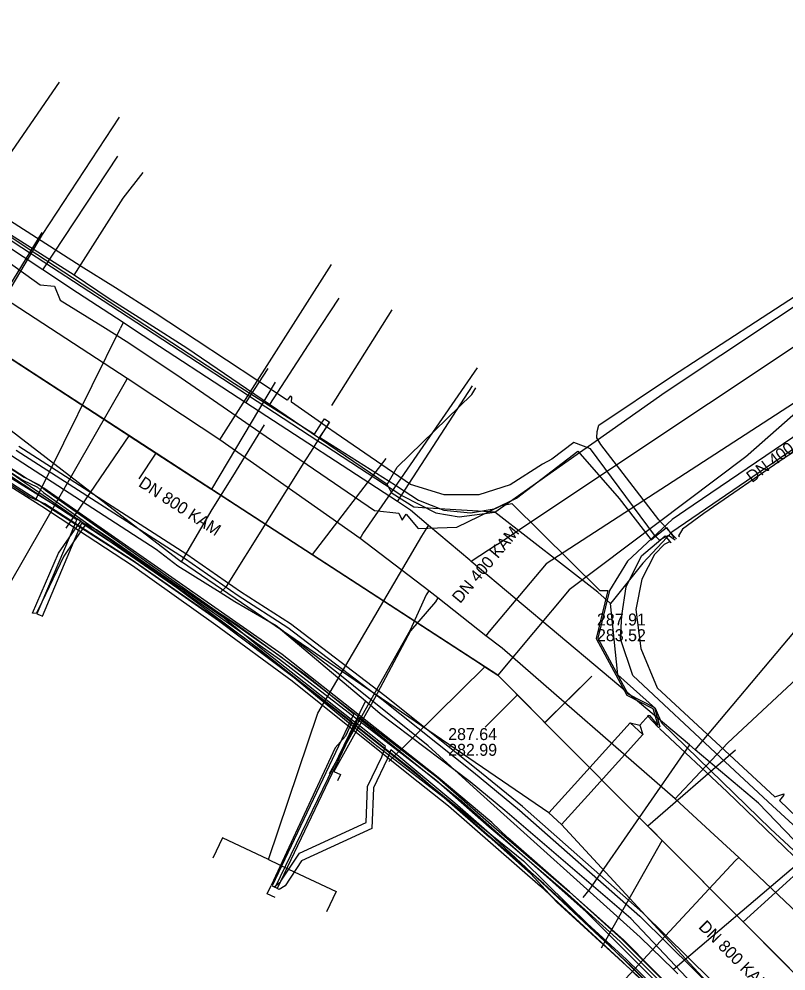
# Model space of a CAD drawing. Extents: x -600309 to -598967, y -1161267 to -1160292.
# Drawn here: x -599995.5 to -599944.1, y -1160430.9 to -1160367.2 of the extents above; entities that cross this region are included whole.
import ezdxf

# ---------------------------------------------------------------- set-up
doc = ezdxf.new("R2010")
doc.units = 0
for name, color, linetype in [('Vrstva 1', 7, 'Continuous'), ('Vrstva 12', 7, 'Continuous'), ('Vrstva 13', 7, 'Continuous'), ('Vrstva 16', 7, 'Continuous'), ('Vrstva 42', 7, 'Continuous'), ('Vrstva 44', 7, 'Continuous'), ('Vrstva 54', 7, 'Continuous'), ('Vrstva 55', 7, 'Continuous'), ('Vrstva 58', 7, 'Continuous'), ('Vrstva 9', 7, 'Continuous')]:
    doc.layers.add(name, color=color, linetype=linetype)

msp = doc.modelspace()

# ---------------------------------------------------------------- linework, layer by layer
at = {"layer": 'Vrstva 1'}
for p, q in [((-599987.41, -1160397.98), (-599986.289, -1160396.256)), ((-599957.13, -1160411.18), (-599960.263, -1160414.296)), ((-599964.26, -1160414.59), (-599962.102, -1160412.446))]:
    msp.add_line(p, q, dxfattribs=at)
for points in [[(-599960.264, -1160414.296), (-599962.102, -1160412.446), (-599963.42, -1160411.12), (-599980.529, -1160400), (-599986.289, -1160396.256), (-599998.233, -1160388.493), (-600002.3, -1160385.85), (-600006.056, -1160383.17), (-600017.139, -1160375.261), (-600022.533, -1160371.412), (-600032.76, -1160364.114), (-600036.59, -1160361.38), (-600042, -1160357.52)], [(-599987.41, -1160397.98), (-599986.29, -1160396.26)], [(-599957.13, -1160411.18), (-599960.26, -1160414.3)], [(-599964.26, -1160414.59), (-599962.102, -1160412.446)], [(-599857.52, -1160559.89), (-599866.111, -1160548.18), (-599871.76, -1160540.48), (-599878.734, -1160527.773), (-599886.327, -1160513.932), (-599890.764, -1160505.846), (-599893.889, -1160500), (-599898.969, -1160490.471), (-599901.936, -1160484.905), (-599902.158, -1160484.489), (-599906.15, -1160477), (-599907.435, -1160475.222), (-599915.237, -1160464.873), (-599922.471, -1160455.22), (-599931.32, -1160443.41), (-599941.55, -1160433.12), (-599946.993, -1160427.644), (-599952.415, -1160422.19), (-599953.381, -1160421.219)]]:
    msp.add_lwpolyline(points, dxfattribs=at)
at = {"layer": 'Vrstva 12'}
for points in [[(-600023.28, -1160363.85), (-599995.26, -1160382.49), (-599989.32, -1160386.36)], [(-599963.61, -1160400.2), (-599952.22, -1160392.16), (-599941.05, -1160384.74), (-599935.56, -1160381.31), (-599924.59, -1160374.96)], [(-599991.77, -1160384.34), (-600002.25, -1160377.7)], [(-599991.77, -1160384.34), (-599988.48, -1160379.19), (-599987.16, -1160377.46)], [(-599973.19, -1160414.27), (-599980.44, -1160408.6), (-599983.72, -1160406.31), (-599987.95, -1160403.37), (-599993.73, -1160399.64), (-599994.74, -1160399.21), (-599997.36, -1160397.53), (-600000.73, -1160395.37), (-600004.83, -1160392.84), (-600017.04, -1160384.87), (-600019.55, -1160383.22), (-600019.64, -1160383.16)], [(-599978.7, -1160393), (-599984.23, -1160389.23), (-599986.75, -1160387.62), (-599989.42, -1160385.91), (-599991.77, -1160384.34)], [(-599974.06, -1160385.87), (-599975.81, -1160388.55)], [(-599989.32, -1160386.36), (-599975.46, -1160395.42)], [(-599975.81, -1160388.55), (-599978.7, -1160393)], [(-599970.82, -1160398.36), (-599970.16, -1160397.2), (-599965.16, -1160392.32), (-599964.88, -1160391.89)], [(-599981.99, -1160405.59), (-599984.83, -1160403.82), (-599986.28, -1160402.71), (-599996.74, -1160395.94), (-599999.28, -1160394.3), (-600000.59, -1160393.46), (-600001.197, -1160393.068)], [(-599970.82, -1160398.36), (-599978.7, -1160393)], [(-599975.46, -1160395.42), (-599974.71, -1160394.23)], [(-599942.26, -1160395.06), (-599951.77, -1160401.55), (-599953.71, -1160403.62), (-599955.67, -1160406.08), (-599955.87, -1160406.32)], [(-599975.89, -1160396.11), (-599975.46, -1160395.42)], [(-599975.46, -1160395.42), (-599975, -1160395.71)], [(-599975, -1160395.71), (-599969.83, -1160399.09), (-599967.56, -1160400.24), (-599966, -1160400.51), (-599963.61, -1160400.2)], [(-599981.99, -1160405.59), (-599981.58, -1160405.18), (-599976.27, -1160396.71), (-599975.89, -1160396.11)], [(-599968.46, -1160399.91), (-599969.03, -1160399.88), (-599970.49, -1160398.95), (-599970.82, -1160398.36)], [(-599963.61, -1160400.2), (-599968.46, -1160399.91)], [(-599955.87, -1160406.32), (-599956.73, -1160405.55), (-599963.61, -1160400.2)], [(-599978.26, -1160407.82), (-599981.01, -1160406.2), (-599981.99, -1160405.59)], [(-599939.98, -1160426.23), (-599945.17, -1160421.41), (-599952.43, -1160414.33), (-599952.87, -1160413.35), (-599955.39, -1160411.09), (-599955.87, -1160406.32)], [(-599977.97, -1160408.04), (-599978.26, -1160407.82)], [(-599972.28, -1160412.85), (-599978.26, -1160407.82)], [(-599964.8, -1160418.85), (-599968.07, -1160415.86), (-599974.32, -1160410.82), (-599977.97, -1160408.04)], [(-599978.32, -1160425.33), (-599972.28, -1160412.85)], [(-599971.28, -1160413.7), (-599972.28, -1160412.85)], [(-599944.48, -1160438.01), (-599950.78, -1160431.36), (-599954.51, -1160427.4), (-599962.95, -1160420.18), (-599965.27, -1160418.25), (-599971.28, -1160413.7)], [(-599973.19, -1160414.27), (-599968.97, -1160417.58), (-599967.01, -1160419.31), (-599964, -1160421.95), (-599961.23, -1160424.4), (-599959.47, -1160426.32), (-599952.75, -1160432.45), (-599949.48, -1160435.72)], [(-599951.66, -1160430.83), (-599953.9, -1160428.65), (-599964.8, -1160418.85)], [(-599978.31, -1160426.01), (-599978.85, -1160425.76), (-599978.59, -1160425.2)], [(-599951.37, -1160431.11), (-599951.66, -1160430.83)]]:
    msp.add_lwpolyline(points, dxfattribs=at)
at = {"layer": 'Vrstva 13'}
for p, q in [((-599960.18, -1160403.66), (-599963.99, -1160408.2)), ((-599963.99, -1160408.2), (-599964.22, -1160408.49))]:
    msp.add_line(p, q, dxfattribs=at)
for points in [[(-599964.22, -1160408.49), (-599967.42, -1160405.94), (-599968.03, -1160405.48), (-599972.62, -1160401.96), (-599982.02, -1160395.37), (-599984.52, -1160393.71), (-599988.214, -1160391.255), (-599996.42, -1160385.9), (-600005.77, -1160380.17), (-600008.31, -1160378.57), (-600012.56, -1160375.88), (-600019.267, -1160371.34), (-600024.36, -1160367.73), (-600031.52, -1160362.48), (-600033.31, -1160361.09), (-600035.67, -1160359.28), (-600040.26, -1160355.47), (-600042.33, -1160353.69)], [(-599894.43, -1160365.84), (-599902.54, -1160369.63), (-599909.986, -1160373.19), (-599920.605, -1160378.688), (-599921.207, -1160379.075), (-599936.343, -1160388.199), (-599960.18, -1160403.66)], [(-599996.42, -1160385.9), (-599996.283, -1160385.655), (-599993.88, -1160381.62), (-599988.727, -1160373.768)], [(-599982.02, -1160395.37), (-599981.9, -1160395.19), (-599974.542, -1160383.628)], [(-599972.62, -1160401.96), (-599972.44, -1160401.66), (-599964.787, -1160390.548)], [(-599988.214, -1160391.255), (-599988.36, -1160391.51), (-599997.209, -1160406.931)], [(-599968.03, -1160405.48), (-599968.21, -1160405.73), (-599969.29, -1160408.11), (-599971.82, -1160412.61), (-599974.701, -1160417.734)], [(-599967.42, -1160405.94), (-599967.59, -1160406.2), (-599969.26, -1160408.15), (-599971.68, -1160412.67), (-599974.39, -1160417.57), (-599973.94, -1160417.78), (-599974.142, -1160418.185)], [(-599902.667, -1160478.427), (-599912.9, -1160463.23), (-599924.79, -1160447.56), (-599925.44, -1160446.75), (-599932.72, -1160438.46), (-599934.77, -1160436.27), (-599943.79, -1160426.66), (-599947.29, -1160423.32), (-599949.5, -1160421.29), (-599951.54, -1160419.4), (-599963.13, -1160409.31), (-599964.22, -1160408.49)], [(-599951.54, -1160419.4), (-599951.31, -1160419.14), (-599948.03, -1160415.65), (-599940.131, -1160408.289)], [(-599973.19, -1160414.27), (-599973.62, -1160415.21), (-599974.31, -1160415.98), (-599978.59, -1160425.2)], [(-599947.29, -1160423.32), (-599947.51, -1160423.53), (-599961.629, -1160438.72), (-599962.193, -1160440.043)], [(-599942.88, -1160423.87), (-599943.15, -1160423.61), (-599943.78, -1160424.14), (-599951.4, -1160430.61), (-599951.66, -1160430.83)]]:
    msp.add_lwpolyline(points, dxfattribs=at)
at = {"layer": 'Vrstva 16'}
for points in [[(-599963.47, -1160402.36), (-599961.01, -1160400.72), (-599937.64, -1160385.15), (-599923.8, -1160377.08), (-599919.49, -1160374.56), (-599912.45, -1160370.78), (-599905.14, -1160366.86), (-599900.61, -1160364.43), (-599893.63, -1160361.35), (-599891.35, -1160360.35), (-599884.67, -1160357.41), (-599873.32, -1160353), (-599871.361, -1160352.261), (-599865.52, -1160350.14), (-599865.3, -1160350.05), (-599864.88, -1160349.89), (-599860.27, -1160348.08), (-599856.17, -1160346.52), (-599819.83, -1160335.69), (-599819.46, -1160335.48), (-599819.06, -1160335.44)], [(-599965.28, -1160403.42), (-599968.05, -1160401.09), (-599969.25, -1160400.08), (-599970.14, -1160399.5), (-599980.29, -1160392.89), (-599987.66, -1160388.06), (-599988.499, -1160387.509), (-599991.54, -1160385.51), (-599993.86, -1160383.97), (-600004.55, -1160376.92), (-600004.622, -1160376.872), (-600013.7, -1160370.88), (-600015.76, -1160369.53), (-600021.6, -1160365.66), (-600038.95, -1160354.2)], [(-599993.86, -1160383.97), (-599988.84, -1160376.36)], [(-599988.499, -1160387.509), (-599988.671, -1160387.887)], [(-599994.354, -1160399.412), (-599988.671, -1160387.887)], [(-599980.29, -1160392.89), (-599978.79, -1160390.59)], [(-599970.14, -1160399.5), (-599965.11, -1160391.74)], [(-599978.76, -1160423.46), (-599975.46, -1160413.662), (-599968.5, -1160401.82), (-599968.05, -1160401.09)], [(-599963.47, -1160402.36), (-599965.19, -1160403.5)], [(-599965.19, -1160403.5), (-599965.28, -1160403.42)], [(-599902.03, -1160473.66), (-599906.22, -1160466.83), (-599917.21, -1160451.71), (-599919.38, -1160448.9), (-599921.83, -1160445.73), (-599925.66, -1160440.77), (-599928.37, -1160437.95), (-599940.64, -1160425.22), (-599945.97, -1160419.69), (-599950.21, -1160416.11), (-599950.59, -1160415.79), (-599965.19, -1160403.5)], [(-599950.21, -1160416.11), (-599943.49, -1160408.12)], [(-599950.59, -1160415.79), (-599957.33, -1160425.52)], [(-599978.76, -1160423.46), (-599981.83, -1160422), (-599982.48, -1160423.36)], [(-599978.76, -1160423.46), (-599977.42, -1160424.1), (-599974.24, -1160425.61), (-599974.89, -1160426.97)], [(-599957.33, -1160425.52), (-599957.73, -1160426)]]:
    msp.add_lwpolyline(points, dxfattribs=at)
at = {"layer": 'Vrstva 42'}
for points in [[(-599951.47, -1160402), (-599951.968, -1160401.459), (-599952.156, -1160401.256), (-599952.65, -1160400.72), (-599956.53, -1160395.68), (-599956.78, -1160395.23), (-599956.77, -1160394.8), (-599956.65, -1160394.38), (-599951.72, -1160391.08), (-599946.17, -1160387.45), (-599940.44, -1160383.74), (-599936.705, -1160381.356), (-599936.21, -1160381.04), (-599934.41, -1160379.87), (-599934.37, -1160379.3), (-599933.9, -1160379.61), (-599928.97, -1160376.92), (-599921.24, -1160372.43), (-599915.61, -1160369.42), (-599907.76, -1160365.37), (-599902.03, -1160362.65), (-599901.43, -1160361.97), (-599899.98, -1160359.11), (-599899.98, -1160359.02)], [(-599997.635, -1160379.114), (-599997.91, -1160379.524), (-599997.995, -1160379.651), (-599997.381, -1160380.028), (-599997.304, -1160379.91), (-599996.512, -1160378.696), (-599996.13, -1160376.351), (-599992.76, -1160371.421)], [(-599951.549, -1160402.07), (-599952.006, -1160401.772), (-599952.163, -1160401.857), (-599952.508, -1160402.043), (-599952.588, -1160402.086), (-599952.861, -1160401.813), (-599952.934, -1160401.741), (-599957.204, -1160395.967), (-599958.338, -1160395.539), (-599959.808, -1160396.653), (-599960.419, -1160396.989), (-599962.599, -1160398.374), (-599964.694, -1160399.048), (-599967.016, -1160399.054), (-599969.258, -1160398.361), (-599974.232, -1160394.938), (-599974.878, -1160394.485), (-599975.206, -1160394.256), (-599977.22, -1160392.844), (-599977.204, -1160392.513), (-599977.321, -1160392.439), (-599977.514, -1160392.703), (-599983.612, -1160388.696), (-599986.342, -1160386.873), (-599989.004, -1160385.192), (-599991.29, -1160383.748), (-599997.304, -1160379.91)], [(-599998.675, -1160380.016), (-599994.262, -1160382.926), (-599981.035, -1160391.583), (-599975.686, -1160394.973), (-599975.206, -1160394.256), (-599975.007, -1160393.959), (-599974.841, -1160394.07), (-599974.675, -1160394.182), (-599974.878, -1160394.485), (-599975.348, -1160395.187), (-599970.272, -1160398.403), (-599968.724, -1160399.394), (-599967.024, -1160400.077), (-599965.244, -1160400.254), (-599963.652, -1160399.976), (-599962.168, -1160399.267), (-599958.068, -1160396.13), (-599955.288, -1160399.284), (-599953.16, -1160402.049), (-599952.861, -1160401.813), (-599952.156, -1160401.256), (-599952.134, -1160401.239), (-599951.968, -1160401.459), (-599951.626, -1160401.915)], [(-599974.531, -1160393.052), (-599970.483, -1160386.651)], [(-599938.19, -1160392.68), (-599944.25, -1160396.58), (-599949.63, -1160400.29), (-599951.06, -1160401.35), (-599951.333, -1160401.782), (-599951.257, -1160401.866)], [(-599889.647, -1160517.995), (-599897.979, -1160502.841), (-599899.24, -1160500.71), (-599900.77, -1160497.971), (-599903.241, -1160493.768), (-599915.215, -1160473.333), (-599916.653, -1160471.11), (-599922.846, -1160462.646), (-599925.156, -1160459.335), (-599929.695, -1160453.144), (-599937.912, -1160443.505), (-599940.759, -1160440.186), (-599941.982, -1160438.954), (-599944.593, -1160436.033), (-599953.705, -1160427.041), (-599961.766, -1160419.921), (-599964.861, -1160417.387), (-599970.985, -1160412.494), (-599977.288, -1160407.684), (-599980.633, -1160405.531), (-599984.223, -1160403.04), (-599995.48, -1160395.806)], [(-599889.647, -1160517.995), (-599897.979, -1160502.841), (-599899.24, -1160500.71), (-599900.77, -1160497.971), (-599903.241, -1160493.768), (-599915.215, -1160473.333), (-599916.653, -1160471.11), (-599922.846, -1160462.646), (-599925.156, -1160459.335), (-599929.695, -1160453.144), (-599937.912, -1160443.505), (-599940.759, -1160440.186), (-599941.982, -1160438.954), (-599944.593, -1160436.033), (-599953.705, -1160427.041), (-599961.766, -1160419.921), (-599964.861, -1160417.387), (-599970.985, -1160412.494), (-599977.288, -1160407.684), (-599980.633, -1160405.531), (-599984.223, -1160403.04), (-599995.48, -1160395.806)], [(-599995.64, -1160396.06), (-599984.39, -1160403.29), (-599980.8, -1160405.78)], [(-599995.64, -1160396.06), (-599984.39, -1160403.29), (-599980.8, -1160405.78)], [(-599997.579, -1160396.764), (-599992.755, -1160399.93), (-599991.585, -1160400.698), (-599992.11, -1160401.934), (-599993.933, -1160406.226), (-599994.263, -1160407.003), (-599994.079, -1160407.081), (-599993.895, -1160407.159), (-599991.76, -1160402.132), (-599991.246, -1160400.921), (-599991.025, -1160401.066), (-599985.457, -1160404.72), (-599980.957, -1160407.673), (-599976.218, -1160411.144), (-599973.05, -1160413.713), (-599973.228, -1160414.087), (-599978.517, -1160425.218), (-599978.376, -1160425.285), (-599978.336, -1160425.304), (-599978.156, -1160425.39), (-599977.927, -1160424.908), (-599972.906, -1160414.342), (-599972.73, -1160413.972), (-599965.836, -1160419.563), (-599957.506, -1160426.969), (-599951.783, -1160432.676)], [(-599946.608, -1160438.419), (-599954.486, -1160430.597), (-599963.982, -1160421.725), (-599966.294, -1160419.68), (-599970.584, -1160416.109), (-599970.82, -1160416.739), (-599971.74, -1160418.672), (-599971.848, -1160421.385), (-599976.544, -1160423.541), (-599977.654, -1160425.22), (-599978.055, -1160425.458), (-599978.392, -1160425.298), (-599978.376, -1160425.285), (-599977.952, -1160424.946), (-599977.927, -1160424.908), (-599976.688, -1160423.034), (-599972.232, -1160420.988), (-599972.136, -1160418.573), (-599971.188, -1160416.581), (-599970.934, -1160415.903), (-599972.906, -1160414.342), (-599973.228, -1160414.087), (-599979.249, -1160409.322), (-599981.737, -1160407.312), (-599985.457, -1160404.72), (-599989.263, -1160402.068), (-599990.272, -1160401.389), (-599990.979, -1160401), (-599991.025, -1160401.066), (-599991.76, -1160402.132), (-599992.456, -1160403.14), (-599993.933, -1160406.226), (-599994.301, -1160406.995), (-599994.555, -1160406.958), (-599992.805, -1160402.941), (-599992.11, -1160401.934), (-599991.332, -1160400.807), (-599992.755, -1160399.93), (-599996.781, -1160397.449)], [(-599943.124, -1160421.628), (-599945.025, -1160419.86), (-599948.506, -1160416.624), (-599954.381, -1160411.147), (-599955.218, -1160408.693), (-599955.125, -1160407.122), (-599954.832, -1160405.211), (-599953.807, -1160403.137), (-599952.508, -1160402.043), (-599952.215, -1160401.796), (-599952.163, -1160401.857), (-599951.898, -1160402.167)], [(-599951.822, -1160402.269), (-599951.933, -1160402.196), (-599952.284, -1160402.372), (-599952.925, -1160403.037), (-599953.789, -1160404.7), (-599954.18, -1160406.719), (-599953.855, -1160409.324), (-599952.759, -1160411.967), (-599944.875, -1160419.258), (-599944.282, -1160419.062), (-599944.289, -1160419.186), (-599944.576, -1160419.52), (-599938.102, -1160425.728)], [(-599980.8, -1160405.78), (-599977.46, -1160407.93), (-599971.17, -1160412.73), (-599965.05, -1160417.62), (-599961.96, -1160420.15), (-599953.91, -1160427.26), (-599944.81, -1160436.24), (-599942.2, -1160439.16), (-599940.98, -1160440.39), (-599938.14, -1160443.7), (-599929.93, -1160453.33), (-599925.4, -1160459.51), (-599923.09, -1160462.82), (-599916.9, -1160471.28), (-599915.47, -1160473.49), (-599903.5, -1160493.92), (-599901.03, -1160498.12), (-599899.5, -1160500.86), (-599898.24, -1160502.99), (-599889.91, -1160518.14)], [(-599980.8, -1160405.78), (-599977.46, -1160407.93), (-599971.17, -1160412.73), (-599965.05, -1160417.62), (-599961.96, -1160420.15), (-599953.91, -1160427.26), (-599944.81, -1160436.24), (-599942.2, -1160439.16), (-599940.98, -1160440.39), (-599938.14, -1160443.7), (-599929.93, -1160453.33), (-599925.4, -1160459.51), (-599923.09, -1160462.82), (-599916.9, -1160471.28), (-599915.47, -1160473.49), (-599903.5, -1160493.92), (-599901.03, -1160498.12), (-599899.5, -1160500.86), (-599898.24, -1160502.99), (-599889.91, -1160518.14)]]:
    msp.add_lwpolyline(points, dxfattribs=at)
at = {"layer": 'Vrstva 44'}
for points in [[(-599905.38, -1160492.26), (-599906.11, -1160491.22), (-599907.117, -1160489.849), (-599907.718, -1160488.816), (-599912.251, -1160481.028), (-599913.037, -1160479.679), (-599914.197, -1160477.659), (-599918.207, -1160471.709), (-599928.467, -1160457.569), (-599929.807, -1160456.049), (-599934.317, -1160450.489), (-599945.727, -1160438.069), (-599951.097, -1160432.799), (-599954.977, -1160428.869), (-599958.627, -1160425.619), (-599962.747, -1160422.009), (-599963.807, -1160420.979), (-599967.407, -1160417.979), (-599977.847, -1160409.739), (-599993.787, -1160398.599), (-599995.027, -1160397.899), (-600016.677, -1160383.869)], [(-600001.81, -1160394.84), (-599993.94, -1160399.81), (-599987.86, -1160403.78), (-599982.28, -1160407.74), (-599977.18, -1160411.5), (-599969.28, -1160417.828), (-599966.72, -1160419.87), (-599960.55, -1160425.25), (-599955.02, -1160430.36), (-599948.81, -1160436.36), (-599943.48, -1160441.87), (-599937.91, -1160448.11), (-599932.55, -1160454.38), (-599927.36, -1160460.79), (-599922.23, -1160467.99), (-599917.44, -1160474.08), (-599913.386, -1160480.552), (-599912.49, -1160482), (-599908.85, -1160487.86), (-599907.3, -1160490.94)], [(-599917.3, -1160473.94), (-599922.07, -1160467.76), (-599927.18, -1160460.63), (-599932.29, -1160454.19), (-599937.65, -1160447.89), (-599943.36, -1160441.63), (-599948.66, -1160436.15), (-599954.81, -1160430.15), (-599960.34, -1160425.09), (-599966.51, -1160419.7), (-599971.73, -1160415.69), (-599977.04, -1160411.3), (-599982.1, -1160407.49), (-599987.69, -1160403.58), (-599993.78, -1160399.7), (-600001.64, -1160394.65)]]:
    msp.add_lwpolyline(points, dxfattribs=at)
at = {"layer": 'Vrstva 54'}
for points in [[(-600001.65, -1160390.39), (-599984.58, -1160403.54)], [(-599981.16, -1160397.82), (-599979.02, -1160394.36)], [(-599982.53, -1160400.02), (-599981.16, -1160397.82)], [(-599984.58, -1160403.54), (-599982.53, -1160400.02)], [(-599960.008, -1160420.332), (-599984.58, -1160403.54)], [(-599956.22, -1160416.15), (-599954.567, -1160414.319)], [(-599953.707, -1160415.092), (-599954.567, -1160414.319), (-599953.915, -1160414.459), (-599953.707, -1160415.092)], [(-599953.915, -1160414.459), (-599953.31, -1160413.79)], [(-599955.34, -1160416.9), (-599953.707, -1160415.092)], [(-599958.29, -1160418.43), (-599956.22, -1160416.15)], [(-599957.4, -1160419.18), (-599955.34, -1160416.9)], [(-599960.008, -1160420.332), (-599958.29, -1160418.43)], [(-599959.15, -1160421.108), (-599957.4, -1160419.18)], [(-599960.008, -1160420.332), (-599959.15, -1160421.108)], [(-599959.15, -1160421.108), (-599941.7, -1160440.04)]]:
    msp.add_lwpolyline(points, dxfattribs=at)
at = {"layer": 'Vrstva 55'}
for points in [[(-599997.25, -1160382.69), (-599994.04, -1160384.98), (-599993.09, -1160385.07), (-599992.7, -1160386), (-599989.85, -1160387.77), (-599988.1, -1160388.87), (-599984.609, -1160391.2), (-599979.35, -1160394.84), (-599971.66, -1160400.09), (-599970.045, -1160400.281), (-599969.81, -1160400.75), (-599969.55, -1160400.34), (-599968.739, -1160401.29), (-599966.159, -1160401.2), (-599963.179, -1160399.75), (-599962.479, -1160399.63), (-599956.58, -1160405.45), (-599956.052, -1160405.441), (-599956.844, -1160408.658), (-599954.794, -1160412.455), (-599953.04, -1160413.361), (-599952.707, -1160414.466), (-599953.231, -1160413.842), (-599953.41, -1160413.84), (-599952.683, -1160414.597), (-599952.59, -1160414.607)], [(-599937.803, -1160391.368), (-599937.909, -1160391.34), (-599938.649, -1160391.55), (-599938.929, -1160392.01), (-599941.87, -1160393.97), (-599950.337, -1160399.737), (-599951.75, -1160400.7), (-599954.74, -1160403.49), (-599955.932, -1160405.454), (-599956.716, -1160408.642), (-599954.706, -1160412.365), (-599952.94, -1160413.279), (-599952.575, -1160414.575)], [(-599952.589, -1160414.7), (-599948.07, -1160418.93), (-599939.74, -1160426.96)]]:
    msp.add_lwpolyline(points, dxfattribs=at)
at = {"layer": 'Vrstva 58'}
for points in [[(-600016.863, -1160384.098), (-599995.207, -1160398.053), (-599994.216, -1160398.54), (-599993.822, -1160398.879), (-599978.036, -1160410.049), (-599967.57, -1160418.126), (-599963.992, -1160421.264), (-599962.912, -1160422.195), (-599958.763, -1160425.764), (-599955.236, -1160428.951), (-599945.799, -1160438.408), (-599934.492, -1160450.715), (-599930.063, -1160456.185), (-599929.433, -1160456.793), (-599928.64, -1160457.944), (-599917.061, -1160474.028), (-599914.371, -1160477.772), (-599913.244, -1160479.838), (-599907.283, -1160489.98), (-599905.165, -1160493.525), (-599904.324, -1160495.376), (-599900.444, -1160501.778), (-599895.47, -1160511.178), (-599888.574, -1160523.607)], [(-600016.752, -1160383.932), (-599995.108, -1160397.869), (-599994.106, -1160398.371), (-599993.683, -1160398.732), (-599977.917, -1160409.889), (-599967.443, -1160417.972), (-599963.861, -1160421.113), (-599962.781, -1160422.043), (-599958.63, -1160425.614), (-599955.098, -1160428.806), (-599945.654, -1160438.27), (-599934.341, -1160450.583), (-599929.932, -1160456.041), (-599929.28, -1160456.665), (-599928.473, -1160457.834), (-599916.899, -1160473.912), (-599914.202, -1160477.666), (-599913.07, -1160479.74), (-599907.111, -1160489.878), (-599904.988, -1160493.432), (-599904.147, -1160495.283), (-599900.269, -1160501.68), (-599895.342, -1160511.014), (-599888.399, -1160523.511)], [(-599996.59, -1160397.17), (-599984.9, -1160405.25), (-599979.35, -1160409.4), (-599968.78, -1160417.81), (-599961.7, -1160423.55), (-599948.48, -1160436.59), (-599942.45, -1160442.14), (-599936.13, -1160449.63), (-599927.53, -1160459.39), (-599916.98, -1160473.97), (-599913.45, -1160480.13), (-599912.61, -1160482.37), (-599909.11, -1160487.85), (-599906.88, -1160490.61), (-599897.04, -1160508.42), (-599889.28, -1160522.54)]]:
    msp.add_lwpolyline(points, dxfattribs=at)
at = {"layer": 'Vrstva 9'}
for p, q in [((-599993.93, -1160381.48), (-599998.233, -1160388.493)), ((-599978.32, -1160391.49), (-599982.571, -1160398.673)), ((-599992.3, -1160401.27), (-599988.08, -1160395.092)), ((-599970.9, -1160396.61), (-599975.846, -1160403.043)), ((-599958.64, -1160405.41), (-599963.42, -1160411.12)), ((-599970.7, -1160416.89), (-599964.284, -1160410.558)), ((-599947.52, -1160416.13), (-599953.381, -1160421.219)), ((-599956.48, -1160429.38), (-599952.415, -1160422.19)), ((-599941.04, -1160422.2), (-599946.993, -1160427.644))]:
    msp.add_line(p, q, dxfattribs=at)
for points in [[(-599933.56, -1160384.82), (-599946.673, -1160396.373), (-599946.688, -1160396.386), (-599946.811, -1160396.494), (-599958.64, -1160405.41)], [(-600002.3, -1160385.85), (-599998.804, -1160388.122), (-599998.233, -1160388.493), (-599988.423, -1160394.869), (-599988.08, -1160395.092), (-599985.849, -1160396.542), (-599982.613, -1160398.646), (-599982.571, -1160398.673), (-599975.846, -1160403.043), (-599975.779, -1160403.087), (-599964.578, -1160410.368), (-599964.284, -1160410.558), (-599963.42, -1160411.12)], [(-599963.42, -1160411.12), (-599961.03, -1160413.524), (-599959.726, -1160414.835), (-599953.381, -1160421.219), (-599953.075, -1160421.526), (-599952.415, -1160422.19), (-599952.269, -1160422.337), (-599946.993, -1160427.644), (-599946.445, -1160428.196), (-599941.342, -1160433.328), (-599933.118, -1160441.601), (-599933.086, -1160441.633), (-599931.32, -1160443.41)]]:
    msp.add_lwpolyline(points, dxfattribs=at)

# ---------------------------------------------------------------- texts
at = {"layer": 'Vrstva 12'}
for s, rotation, p in [('DN 400 BET', 37.00682, (-599946.403, -1160398.267)), ('DN 800 KAM', 326.9782, (-599987.522, -1160398.433)), ('DN 400 KAM', 50.06636, (-599965.939, -1160406.364)), ('DN 800 KAM', 314.83093, (-599950.034, -1160428.019))]:
    msp.add_text(s, height=0.8, rotation=rotation, dxfattribs=at).set_placement(p)
for s, p in [('287.91', (-599956.781, -1160407.792)), ('283.52', (-599956.781, -1160408.842)), ('287.64', (-599966.74, -1160415.466)), ('282.99', (-599966.74, -1160416.516))]:
    msp.add_text(s, height=0.8, dxfattribs=at).set_placement(p)

doc.saveas('drawing.dxf')
